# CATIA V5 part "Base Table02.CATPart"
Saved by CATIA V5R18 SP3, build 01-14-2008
Part number: Base Table
Bounding box of the stored display mesh (mm): x -350 to 350, y -185 to 185, z 0 to 12
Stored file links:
  E:\#00 CATIA V5 Movie\#03 CATIA V5 Data\#07 KIN\Balance Unit (1)\Base Table02.CATPart
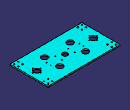
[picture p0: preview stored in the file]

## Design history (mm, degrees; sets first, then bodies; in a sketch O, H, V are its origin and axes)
Body1 "PartBody" (main body)
  Solid1: solid without history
